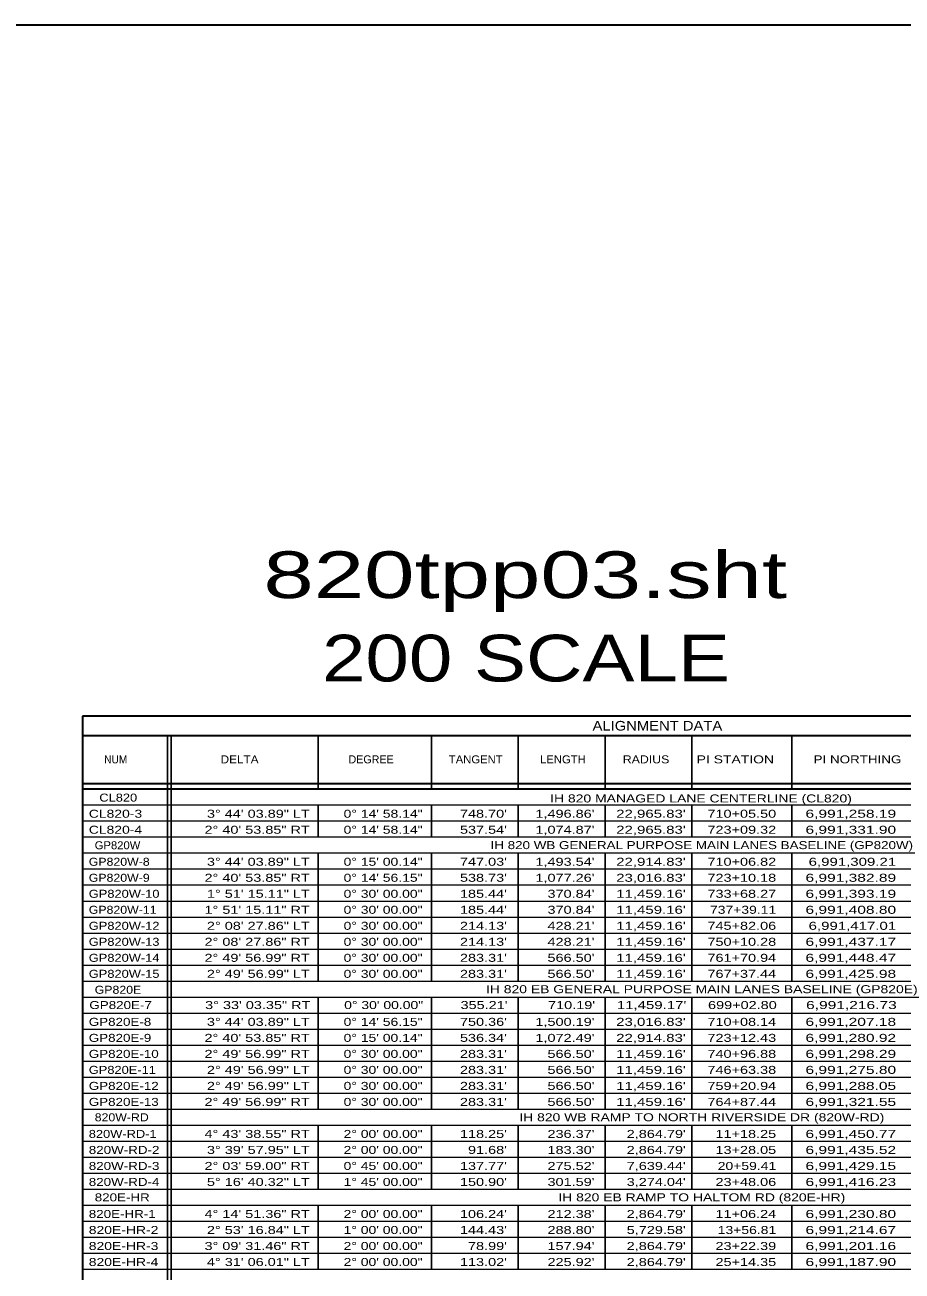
# Model space of a CAD drawing. Extents: x 1953053 to 1967065, y 7363860 to 7371201.
# Drawn here: x 1957841 to 1959156, y 7369333 to 7371201 of the extents above; entities that cross this region are included whole.
import ezdxf
from ezdxf.enums import TextEntityAlignment as Align

# ---------------------------------------------------------------- set-up
doc = ezdxf.new("R2010")
doc.units = 0
doc.header["$LTSCALE"] = 4.8
doc.layers.add('10', color=7, linetype='Continuous')
doc.layers.add('12', color=7, linetype='Continuous', lineweight=25)
doc.layers.add('62', color=7, linetype='Continuous', lineweight=35)

msp = doc.modelspace()

# ---------------------------------------------------------------- linework, layer by layer
at = {"layer": '12', "lineweight": 35}
for p, q in [((1959650.637, 7370164.879), (1957927.305, 7370164.879)), ((1957927.305, 7370164.879), (1957927.305, 7368423.747)), ((1957927.305, 7370136.079), (1959650.637, 7370136.079)), ((1957927.305, 7370064.079), (1959650.637, 7370064.079)), ((1957927.305, 7370055.746), (1959650.637, 7370055.746))]:
    msp.add_line(p, q, dxfattribs=at)
at = {"layer": '12'}
for p, q in [((1958055.15, 7370136.079), (1958055.15, 7368423.747)), ((1958060.637, 7370136.079), (1958060.637, 7368423.747)), ((1958280.637, 7370136.079), (1958280.637, 7370055.746)), ((1958450.637, 7370136.079), (1958450.637, 7370055.746)), ((1958580.637, 7370136.079), (1958580.637, 7370055.746)), ((1958710.637, 7370136.079), (1958710.637, 7370055.746)), ((1958840.637, 7370136.079), (1958840.637, 7370055.746)), ((1958990.637, 7370136.079), (1958990.637, 7370055.746)), ((1958055.15, 7370114.479), (1958055.15, 7369838.526)), ((1958280.637, 7370031.746), (1958280.637, 7369983.746)), ((1958450.637, 7370031.746), (1958450.637, 7369983.746)), ((1958580.637, 7370031.746), (1958580.637, 7369983.746)), ((1958710.637, 7370031.746), (1958710.637, 7369983.746)), ((1958840.637, 7370031.746), (1958840.637, 7369983.746)), ((1958990.637, 7370031.746), (1958990.637, 7369983.746)), ((1958280.637, 7369959.746), (1958280.637, 7369767.746)), ((1958450.637, 7369959.746), (1958450.637, 7369767.746)), ((1958580.637, 7369959.746), (1958580.637, 7369767.746)), ((1958710.637, 7369959.746), (1958710.637, 7369767.746)), ((1958840.637, 7369959.746), (1958840.637, 7369767.746)), ((1958990.637, 7369959.746), (1958990.637, 7369767.746)), ((1958280.637, 7369743.746), (1958280.637, 7369575.746)), ((1958450.637, 7369743.746), (1958450.637, 7369575.746)), ((1958580.637, 7369743.746), (1958580.637, 7369575.746)), ((1958710.637, 7369743.746), (1958710.637, 7369575.746)), ((1958840.637, 7369743.746), (1958840.637, 7369575.746)), ((1958990.637, 7369743.746), (1958990.637, 7369575.746)), ((1958280.637, 7369551.746), (1958280.637, 7369455.746)), ((1958450.637, 7369551.746), (1958450.637, 7369455.746)), ((1958580.637, 7369551.746), (1958580.637, 7369455.746)), ((1958710.637, 7369551.746), (1958710.637, 7369455.746)), ((1958840.637, 7369551.746), (1958840.637, 7369455.746)), ((1958990.637, 7369551.746), (1958990.637, 7369455.746)), ((1958280.637, 7369431.746), (1958280.637, 7369335.746)), ((1958450.637, 7369431.746), (1958450.637, 7369335.746)), ((1958580.637, 7369431.746), (1958580.637, 7369335.746)), ((1958710.637, 7369431.746), (1958710.637, 7369335.746)), ((1958840.637, 7369431.746), (1958840.637, 7369335.746)), ((1958990.637, 7369431.746), (1958990.637, 7369335.746))]:
    msp.add_line(p, q, dxfattribs=at)
at = {"layer": '12', "lineweight": 13}
for p, q in [((1957927.305, 7370007.746), (1959650.637, 7370007.746)), ((1957927.305, 7369983.746), (1959650.637, 7369983.746)), ((1957927.305, 7369959.746), (1959650.637, 7369959.746)), ((1957927.305, 7369935.746), (1959650.637, 7369935.746)), ((1957927.305, 7369911.746), (1959650.637, 7369911.746)), ((1957927.305, 7369887.746), (1959650.637, 7369887.746)), ((1957927.305, 7369863.746), (1959650.637, 7369863.746)), ((1957927.305, 7369839.746), (1959650.637, 7369839.746)), ((1957927.305, 7369815.746), (1959650.637, 7369815.746)), ((1957927.305, 7369791.746), (1959650.637, 7369791.746)), ((1957927.305, 7369767.746), (1959650.637, 7369767.746)), ((1957927.305, 7369743.746), (1959650.637, 7369743.746)), ((1957927.305, 7369719.746), (1959650.637, 7369719.746)), ((1957927.305, 7369695.746), (1959650.637, 7369695.746)), ((1957927.305, 7369671.746), (1959650.637, 7369671.746)), ((1957927.305, 7369647.746), (1959650.637, 7369647.746)), ((1957927.305, 7369623.746), (1959650.637, 7369623.746)), ((1957927.305, 7369599.746), (1959650.637, 7369599.746)), ((1957927.305, 7369551.746), (1959650.637, 7369551.746)), ((1957927.305, 7369527.746), (1959650.637, 7369527.746)), ((1957927.305, 7369503.746), (1959650.637, 7369503.746)), ((1957927.305, 7369479.746), (1959650.637, 7369479.746)), ((1957927.305, 7369455.746), (1959650.637, 7369455.746)), ((1957927.305, 7369431.746), (1959650.637, 7369431.746)), ((1957927.305, 7369407.746), (1959650.637, 7369407.746)), ((1957927.305, 7369383.746), (1959650.637, 7369383.746)), ((1957927.305, 7369359.746), (1959650.637, 7369359.746)), ((1957927.305, 7369335.746), (1959650.637, 7369335.746))]:
    msp.add_line(p, q, dxfattribs=at)
for points in [[(1957927.305, 7370031.746), (1958712.39, 7370031.746), (1959650.637, 7370031.746)], [(1957927.305, 7369575.746), (1959174.539, 7369575.746), (1959650.637, 7369575.746)]]:
    msp.add_lwpolyline(points, dxfattribs=at)
at = {"layer": '62'}
msp.add_lwpolyline([(1953052.784, 7371201.108), (1967065.314, 7371201.108), (1967065.314, 7363859.877), (1953052.784, 7363859.877)], close=True, dxfattribs=at)

# ---------------------------------------------------------------- texts
at = {"layer": '10'}
for s, width, p in [('CL820', 1.2, (1957952.711, 7370036.747)), ('CL820-3', 1.3, (1957936.926, 7370012.573)), ('CL820-4', 1.3, (1957936.926, 7369988.573)), ('GP820W', 1.05, (1957945.832, 7369965.298)), ('GP820W-8', 1.15, (1957936.926, 7369940.573)), ('GP820W-9', 1.15, (1957936.926, 7369916.573)), ('GP820W-10', 1.2, (1957936.926, 7369892.573)), ('GP820W-11', 1.15, (1957936.926, 7369868.573)), ('GP820W-12', 1.2, (1957936.926, 7369844.573)), ('GP820W-13', 1.2, (1957936.926, 7369820.573)), ('GP820W-14', 1.2, (1957936.926, 7369796.573)), ('GP820W-15', 1.2, (1957936.926, 7369772.573)), ('GP820E', 1.15, (1957945.832, 7369748.669)), ('GP820E-7', 1.25, (1957937.8, 7369725.764)), ('GP820E-8', 1.25, (1957936.926, 7369700.573)), ('GP820E-9', 1.25, (1957936.926, 7369676.573)), ('GP820E-10', 1.25, (1957936.926, 7369652.573)), ('GP820E-11', 1.2, (1957936.926, 7369628.573)), ('GP820E-12', 1.25, (1957936.926, 7369604.573)), ('GP820E-13', 1.25, (1957936.926, 7369580.573)), ('820W-RD', 1.15, (1957945.832, 7369557.47)), ('820W-RD-1', 1.2, (1957936.926, 7369532.573)), ('820W-RD-2', 1.25, (1957936.926, 7369508.573)), ('820W-RD-3', 1.25, (1957936.926, 7369484.573)), ('820W-RD-4', 1.25, (1957936.926, 7369460.573)), ('820E-HR', 1.25, (1957945.832, 7369437.47)), ('820E-HR-1', 1.25, (1957936.926, 7369412.573)), ('820E-HR-2', 1.3, (1957936.926, 7369388.573)), ('820E-HR-3', 1.3, (1957936.926, 7369364.573)), ('820E-HR-4', 1.3, (1957936.926, 7369340.573))]:
    msp.add_text(s, height=12, dxfattribs=dict(at, width=width)).set_placement(p)
for s, width, p in [('IH 820 MANAGED LANE CENTERLINE (CL820)', 1.3, (1958854.428, 7370035.509)), ('IH 820 WB GENERAL PURPOSE MAIN LANES BASELINE (GP820W)', 1.25, (1958855.637, 7369965.54)), ('IH 820 EB GENERAL PURPOSE MAIN LANES BASELINE (GP820E)', 1.3, (1958855.637, 7369749.54)), ('IH 820 WB RAMP TO NORTH RIVERSIDE DR (820W-RD)', 1.3, (1958855.637, 7369557.54)), ('IH 820 EB RAMP TO HALTOM RD (820E-HR)', 1.3, (1958855.637, 7369437.54))]:
    msp.add_text(s, height=12, dxfattribs=dict(at, width=width)).set_placement(p, align=Align.CENTER)
for s, width, p in [('3° 44\' 03.89" LT', 1.35, (1958268.159, 7370012.573)), ('0° 14\' 58.14"', 1.3, (1958437.154, 7370012.573)), ("748.70'", 1.35, (1958563.564, 7370012.573)), ("1,496.86'", 1.35, (1958694.761, 7370012.573)), ("22,965.83'", 1.4, (1958831.53, 7370012.573)), ('710+05.50', 1.35, (1958967.074, 7370012.573)), ('6,991,258.19', 1.45, (1959146.839, 7370012.573)), ('2° 40\' 53.85" RT', 1.35, (1958268.159, 7369988.573)), ('0° 14\' 58.14"', 1.3, (1958437.154, 7369988.573)), ("537.54'", 1.35, (1958563.564, 7369988.573)), ("1,074.87'", 1.35, (1958694.761, 7369988.573)), ("22,965.83'", 1.4, (1958831.53, 7369988.573)), ('723+09.32', 1.35, (1958967.074, 7369988.573)), ('6,991,331.90', 1.45, (1959146.839, 7369988.573)), ('3° 44\' 03.89" LT', 1.35, (1958268.159, 7369940.573)), ('0° 15\' 00.14"', 1.3, (1958437.154, 7369940.573)), ("747.03'", 1.35, (1958563.564, 7369940.573)), ("1,493.54'", 1.35, (1958694.761, 7369940.573)), ("22,914.83'", 1.4, (1958831.53, 7369940.573)), ('710+06.82', 1.35, (1958967.074, 7369940.573)), ('6,991,309.21', 1.4, (1959146.839, 7369940.573)), ('2° 40\' 53.85" RT', 1.35, (1958268.159, 7369916.573)), ('0° 14\' 56.15"', 1.3, (1958437.154, 7369916.573)), ("538.73'", 1.35, (1958563.564, 7369916.573)), ("1,077.26'", 1.35, (1958694.761, 7369916.573)), ("23,016.83'", 1.4, (1958831.53, 7369916.573)), ('723+10.18', 1.35, (1958967.074, 7369916.573)), ('6,991,382.89', 1.45, (1959146.839, 7369916.573)), ('1° 51\' 15.11" LT', 1.35, (1958268.159, 7369892.573)), ('0° 30\' 00.00"', 1.3, (1958437.154, 7369892.573)), ("185.44'", 1.35, (1958563.564, 7369892.573)), ("370.84'", 1.35, (1958694.761, 7369892.573)), ("11,459.16'", 1.4, (1958831.53, 7369892.573)), ('733+68.27', 1.35, (1958967.074, 7369892.573)), ('6,991,393.19', 1.45, (1959146.839, 7369892.573)), ('1° 51\' 15.11" RT', 1.35, (1958268.159, 7369868.573)), ('0° 30\' 00.00"', 1.3, (1958437.154, 7369868.573)), ("185.44'", 1.35, (1958563.564, 7369868.573)), ("370.84'", 1.35, (1958694.761, 7369868.573)), ("11,459.16'", 1.4, (1958831.53, 7369868.573)), ('737+39.11', 1.3, (1958967.074, 7369868.573)), ('6,991,408.80', 1.45, (1959146.839, 7369868.573)), ('2° 08\' 27.86" LT', 1.35, (1958268.159, 7369844.573)), ('0° 30\' 00.00"', 1.3, (1958437.154, 7369844.573)), ("214.13'", 1.35, (1958563.564, 7369844.573)), ("428.21'", 1.35, (1958694.761, 7369844.573)), ("11,459.16'", 1.4, (1958831.53, 7369844.573)), ('745+82.06', 1.35, (1958967.074, 7369844.573)), ('6,991,417.01', 1.4, (1959146.839, 7369844.573)), ('2° 08\' 27.86" RT', 1.35, (1958268.159, 7369820.573)), ('0° 30\' 00.00"', 1.3, (1958437.154, 7369820.573)), ("214.13'", 1.35, (1958563.564, 7369820.573)), ("428.21'", 1.35, (1958694.761, 7369820.573)), ("11,459.16'", 1.4, (1958831.53, 7369820.573)), ('750+10.28', 1.35, (1958967.074, 7369820.573)), ('6,991,437.17', 1.45, (1959146.839, 7369820.573)), ('2° 49\' 56.99" RT', 1.35, (1958268.159, 7369796.573)), ('0° 30\' 00.00"', 1.3, (1958437.154, 7369796.573)), ("283.31'", 1.35, (1958563.564, 7369796.573)), ("566.50'", 1.35, (1958694.761, 7369796.573)), ("11,459.16'", 1.4, (1958831.53, 7369796.573)), ('761+70.94', 1.35, (1958967.074, 7369796.573)), ('6,991,448.47', 1.45, (1959146.839, 7369796.573)), ('2° 49\' 56.99" LT', 1.35, (1958268.159, 7369772.573)), ('0° 30\' 00.00"', 1.3, (1958437.154, 7369772.573)), ("283.31'", 1.35, (1958563.564, 7369772.573)), ("566.50'", 1.35, (1958694.761, 7369772.573)), ("11,459.16'", 1.4, (1958831.53, 7369772.573)), ('767+37.44', 1.35, (1958967.074, 7369772.573)), ('6,991,425.98', 1.45, (1959146.839, 7369772.573)), ('3° 33\' 03.35" RT', 1.35, (1958269.033, 7369725.764)), ('0° 30\' 00.00"', 1.3, (1958438.028, 7369725.764)), ("355.21'", 1.35, (1958564.438, 7369725.764)), ("710.19'", 1.35, (1958695.635, 7369725.764)), ("11,459.17'", 1.4, (1958832.404, 7369725.764)), ('699+02.80', 1.35, (1958967.948, 7369725.764)), ('6,991,216.73', 1.45, (1959147.713, 7369725.764)), ('3° 44\' 03.89" LT', 1.35, (1958268.159, 7369700.573)), ('0° 14\' 56.15"', 1.3, (1958437.154, 7369700.573)), ("750.36'", 1.35, (1958563.564, 7369700.573)), ("1,500.19'", 1.35, (1958694.761, 7369700.573)), ("23,016.83'", 1.4, (1958831.53, 7369700.573)), ('710+08.14', 1.35, (1958967.074, 7369700.573)), ('6,991,207.18', 1.45, (1959146.839, 7369700.573)), ('2° 40\' 53.85" RT', 1.35, (1958268.159, 7369676.573)), ('0° 15\' 00.14"', 1.3, (1958437.154, 7369676.573)), ("536.34'", 1.35, (1958563.564, 7369676.573)), ("1,072.49'", 1.35, (1958694.761, 7369676.573)), ("22,914.83'", 1.4, (1958831.53, 7369676.573)), ('723+12.43', 1.35, (1958967.074, 7369676.573)), ('6,991,280.92', 1.45, (1959146.839, 7369676.573)), ('2° 49\' 56.99" RT', 1.35, (1958268.159, 7369652.573)), ('0° 30\' 00.00"', 1.3, (1958437.154, 7369652.573)), ("283.31'", 1.35, (1958563.564, 7369652.573)), ("566.50'", 1.35, (1958694.761, 7369652.573)), ("11,459.16'", 1.4, (1958831.53, 7369652.573)), ('740+96.88', 1.35, (1958967.074, 7369652.573)), ('6,991,298.29', 1.45, (1959146.839, 7369652.573)), ('2° 49\' 56.99" LT', 1.35, (1958268.159, 7369628.573)), ('0° 30\' 00.00"', 1.3, (1958437.154, 7369628.573)), ("283.31'", 1.35, (1958563.564, 7369628.573)), ("566.50'", 1.35, (1958694.761, 7369628.573)), ("11,459.16'", 1.4, (1958831.53, 7369628.573)), ('746+63.38', 1.35, (1958967.074, 7369628.573)), ('6,991,275.80', 1.45, (1959146.839, 7369628.573)), ('2° 49\' 56.99" LT', 1.35, (1958268.159, 7369604.573)), ('0° 30\' 00.00"', 1.3, (1958437.154, 7369604.573)), ("283.31'", 1.35, (1958563.564, 7369604.573)), ("566.50'", 1.35, (1958694.761, 7369604.573)), ("11,459.16'", 1.4, (1958831.53, 7369604.573)), ('759+20.94', 1.35, (1958967.074, 7369604.573)), ('6,991,288.05', 1.45, (1959146.839, 7369604.573)), ('2° 49\' 56.99" RT', 1.35, (1958268.159, 7369580.573)), ('0° 30\' 00.00"', 1.3, (1958437.154, 7369580.573)), ("283.31'", 1.35, (1958563.564, 7369580.573)), ("566.50'", 1.35, (1958694.761, 7369580.573)), ("11,459.16'", 1.4, (1958831.53, 7369580.573)), ('764+87.44', 1.35, (1958967.074, 7369580.573)), ('6,991,321.55', 1.45, (1959146.839, 7369580.573)), ('4° 43\' 38.55" RT', 1.35, (1958268.159, 7369532.573)), ('2° 00\' 00.00"', 1.3, (1958437.154, 7369532.573)), ("118.25'", 1.35, (1958563.564, 7369532.573)), ("236.37'", 1.35, (1958694.761, 7369532.573)), ("2,864.79'", 1.35, (1958831.53, 7369532.573)), ('11+18.25', 1.35, (1958967.074, 7369532.573)), ('6,991,450.77', 1.45, (1959146.839, 7369532.573)), ('3° 39\' 57.95" LT', 1.35, (1958268.159, 7369508.573)), ('2° 00\' 00.00"', 1.3, (1958437.154, 7369508.573)), ("91.68'", 1.35, (1958563.564, 7369508.573)), ("183.30'", 1.35, (1958694.761, 7369508.573)), ("2,864.79'", 1.35, (1958831.53, 7369508.573)), ('13+28.05', 1.35, (1958967.074, 7369508.573)), ('6,991,435.52', 1.45, (1959146.839, 7369508.573)), ('2° 03\' 59.00" RT', 1.35, (1958268.159, 7369484.573)), ('0° 45\' 00.00"', 1.3, (1958437.154, 7369484.573)), ("137.77'", 1.35, (1958563.564, 7369484.573)), ("275.52'", 1.35, (1958694.761, 7369484.573)), ("7,639.44'", 1.35, (1958831.53, 7369484.573)), ('20+59.41', 1.3, (1958967.074, 7369484.573)), ('6,991,429.15', 1.45, (1959146.839, 7369484.573)), ('5° 16\' 40.32" LT', 1.35, (1958268.159, 7369460.573)), ('1° 45\' 00.00"', 1.3, (1958437.154, 7369460.573)), ("150.90'", 1.35, (1958563.564, 7369460.573)), ("301.59'", 1.35, (1958694.761, 7369460.573)), ("3,274.04'", 1.35, (1958831.53, 7369460.573)), ('23+48.06', 1.35, (1958967.074, 7369460.573)), ('6,991,416.23', 1.45, (1959146.839, 7369460.573)), ('4° 14\' 51.36" RT', 1.35, (1958268.159, 7369412.573)), ('2° 00\' 00.00"', 1.3, (1958437.154, 7369412.573)), ("106.24'", 1.35, (1958563.564, 7369412.573)), ("212.38'", 1.35, (1958694.761, 7369412.573)), ("2,864.79'", 1.35, (1958831.53, 7369412.573)), ('11+06.24', 1.35, (1958967.074, 7369412.573)), ('6,991,230.80', 1.45, (1959146.839, 7369412.573)), ('2° 53\' 16.84" LT', 1.35, (1958268.159, 7369388.573)), ('1° 00\' 00.00"', 1.3, (1958437.154, 7369388.573)), ("144.43'", 1.35, (1958563.564, 7369388.573)), ("288.80'", 1.35, (1958694.761, 7369388.573)), ("5,729.58'", 1.35, (1958831.53, 7369388.573)), ('13+56.81', 1.3, (1958967.074, 7369388.573)), ('6,991,214.67', 1.45, (1959146.839, 7369388.573)), ('3° 09\' 31.46" RT', 1.35, (1958268.159, 7369364.573)), ('2° 00\' 00.00"', 1.3, (1958437.154, 7369364.573)), ("78.99'", 1.35, (1958563.564, 7369364.573)), ("157.94'", 1.35, (1958694.761, 7369364.573)), ("2,864.79'", 1.35, (1958831.53, 7369364.573)), ('23+22.39', 1.35, (1958967.074, 7369364.573)), ('6,991,201.16', 1.45, (1959146.839, 7369364.573)), ('4° 31\' 06.01" LT', 1.35, (1958268.159, 7369340.573)), ('2° 00\' 00.00"', 1.3, (1958437.154, 7369340.573)), ("113.02'", 1.35, (1958563.564, 7369340.573)), ("225.92'", 1.35, (1958694.761, 7369340.573)), ("2,864.79'", 1.35, (1958831.53, 7369340.573)), ('25+14.35', 1.35, (1958967.074, 7369340.573)), ('6,991,187.90', 1.45, (1959146.839, 7369340.573))]:
    msp.add_text(s, height=12, dxfattribs=dict(at, width=width)).set_placement(p, align=Align.RIGHT)
at = {"layer": '12'}
for s, height, width, p in [('ALIGNMENT DATA', 14.4, 1.15, (1958789.078, 7370143.278)), ('NUM', 12, 0.95, (1957977.352, 7370094.075)), ('DELTA', 12, 1.1, (1958162.927, 7370094.078)), ('TANGENT', 12, 1.05, (1958516.825, 7370094.078)), ('LENGTH', 12, 1.05, (1958647.46, 7370094.078)), ('RADIUS', 12, 1.15, (1958772.07, 7370094.078)), ('PI STATION', 12, 1.3, (1958905.874, 7370094.078)), ('PI NORTHING', 12, 1.25, (1959088.95, 7370094.078))]:
    msp.add_text(s, height=height, dxfattribs=dict(at, width=width)).set_placement(p, align=Align.CENTER)
msp.add_text('DEGREE', height=12, dxfattribs=at).set_placement((1958360.014, 7370094.078), align=Align.CENTER)
at = {"layer": '62'}
for s, width, p in [('820tpp03.sht', 1.45, (1958591.061, 7370341.878)), ('200 SCALE', 1.25, (1958592.17, 7370216.878))]:
    msp.add_text(s, height=70, dxfattribs=dict(at, width=width)).set_placement(p, align=Align.CENTER)

doc.saveas('drawing.dxf')
